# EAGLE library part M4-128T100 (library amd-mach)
AMD MACH SERIES
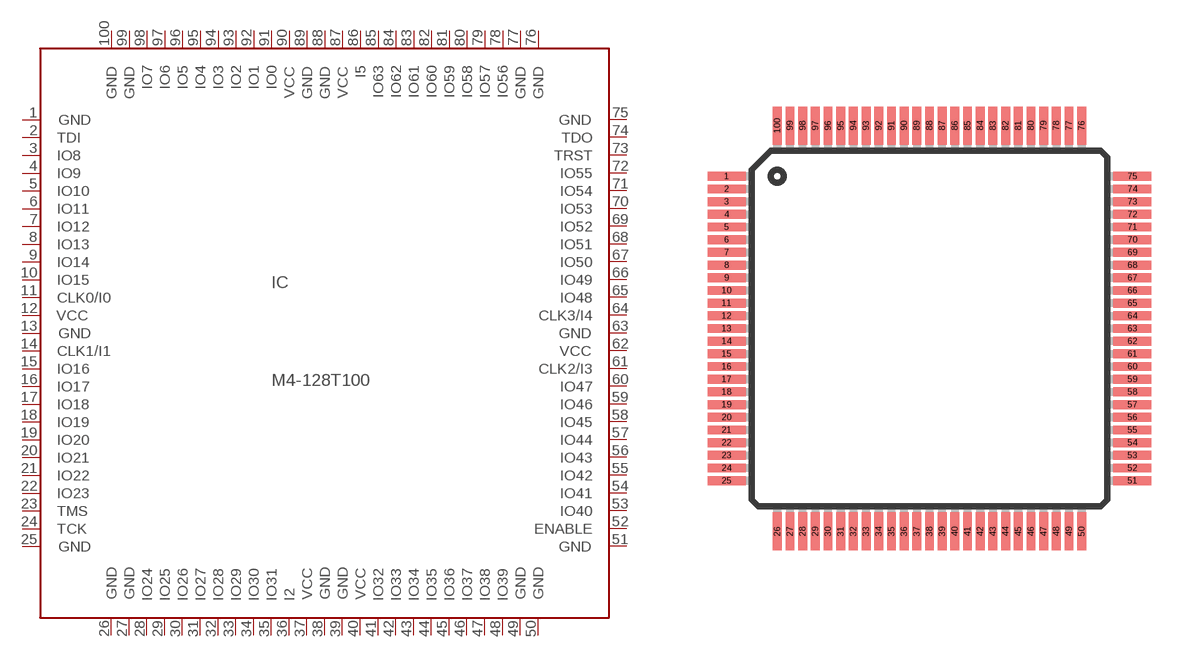
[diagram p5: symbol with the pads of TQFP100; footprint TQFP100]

Designator prefix IC

## M4-128T100 (OC_FARNELL: unknown; OC_NEWARK: unknown)  [TQFP100]
1  GND  pwr
2  TDI  in
3  IO8
4  IO9
5  IO10
6  IO11
7  IO12
8  IO13
9  IO14
10  IO15
11  CLK0/I0  in
12  VCC  pwr
13  GND  pwr
14  CLK1/I1  in
15  IO16
16  IO17
17  IO18
18  IO19
19  IO20
20  IO21
21  IO22
22  IO23
23  TMS  in
24  TCK  in
25  GND  pwr
26  GND  pwr
27  GND  pwr
28  IO24
29  IO25
30  IO26
31  IO27
32  IO28
33  IO29
34  IO30
35  IO31
36  I2  in
37  VCC  pwr
38  GND  pwr
39  GND  pwr
40  VCC  pwr
41  IO32
42  IO33
43  IO34
44  IO35
45  IO36
46  IO37
47  IO38
48  IO39
49  GND  pwr
50  GND  pwr
51  GND  pwr
52  ENABLE  in
53  IO40
54  IO41
55  IO42
56  IO43
57  IO44
58  IO45
59  IO46
60  IO47
61  CLK2/I3  in
62  VCC  pwr
63  GND  pwr
64  CLK3/I4  in
65  IO48
66  IO49
67  IO50
68  IO51
69  IO52
70  IO53
71  IO54
72  IO55
73  TRST  in
74  TDO  out
75  GND  pwr
76  GND  pwr
77  GND  pwr
78  IO56
79  IO57
80  IO58
81  IO59
82  IO60
83  IO61
84  IO62
85  IO63
86  I5  in
87  VCC  pwr
88  GND  pwr
89  GND  pwr
90  VCC  pwr
91  IO0
92  IO1
93  IO2
94  IO3
95  IO4
96  IO5
97  IO6
98  IO7
99  GND  pwr
100  GND  pwr

## Footprint TQFP100 (pad centres in mm)
THIN QUAD FLAT PACK
smd 1.5 x 0.35: 1 -8,6; 2 -8,5.5; 3 -8,5; 4 -8,4.5; 5 -8,4; 6 -8,3.5; 7 -8,3; 8 -8,2.5; 9 -8,2; 10 -8,1.5; 11 -8,1; 12 -8,0.5; 13 -8,0; 14 -8,-0.5; 15 -8,-1; 16 -8,-1.5; 17 -8,-2; 18 -8,-2.5; 19 -8,-3; 20 -8,-3.5; 21 -8,-4; 22 -8,-4.5; 23 -8,-5; 24 -8,-5.5; 25 -8,-6; 51 8,-6; 52 8,-5.5; 53 8,-5; 54 8,-4.5; 55 8,-4; 56 8,-3.5; 57 8,-3; 58 8,-2.5; 59 8,-2; 60 8,-1.5; 61 8,-1; 62 8,-0.5; 63 8,0; 64 8,0.5; 65 8,1; 66 8,1.5; 67 8,2; 68 8,2.5; 69 8,3; 70 8,3.5; 71 8,4; 72 8,4.5; 73 8,5; 74 8,5.5; 75 8,6
smd 0.35 x 1.5: 26 -6,-8; 27 -5.5,-8; 28 -5,-8; 29 -4.5,-8; 30 -4,-8; 31 -3.5,-8; 32 -3,-8; 33 -2.5,-8; 34 -2,-8; 35 -1.5,-8; 36 -1,-8; 37 -0.5,-8; 38 0,-8; 39 0.5,-8; 40 1,-8; 41 1.5,-8; 42 2,-8; 43 2.5,-8; 44 3,-8; 45 3.5,-8; 46 4,-8; 47 4.5,-8; 48 5,-8; 49 5.5,-8; 50 6,-8; 76 6,8; 77 5.5,8; 78 5,8; 79 4.5,8; 80 4,8; 81 3.5,8; 82 3,8; 83 2.5,8; 84 2,8; 85 1.5,8; 86 1,8; 87 0.5,8; 88 0,8; 89 -0.5,8; 90 -1,8; 91 -1.5,8; 92 -2,8; 93 -2.5,8; 94 -3,8; 95 -3.5,8; 96 -4,8; 97 -4.5,8; 98 -5,8; 99 -5.5,8; 100 -6,8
